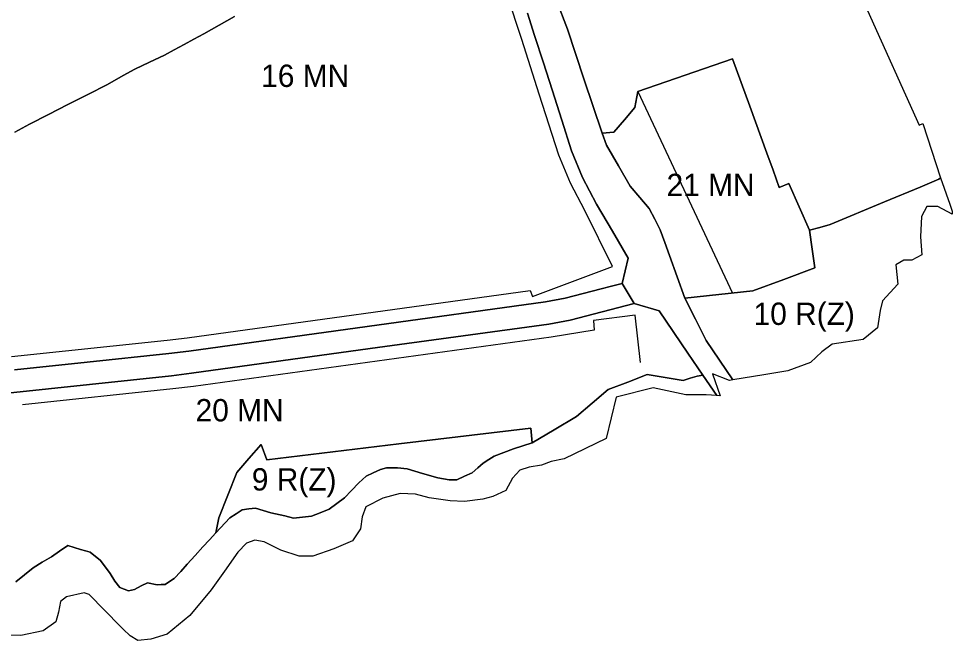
# Model space of a CAD drawing. Extents: x 7423432 to 7425824, y 5537848 to 5539677.
# Drawn here: x 7425406.3 to 7425824.2, y 5538340.3 to 5538618.6 of the extents above; entities that cross this region are included whole.
import ezdxf

# ---------------------------------------------------------------- set-up
doc = ezdxf.new("R2010")
doc.units = 0
for name, color, linetype in [('linie_rozgraniczajace', 7, 'Continuous'), ('linie_zabudowy_nieprzekraczalne', 7, 'Continuous'), ('oznaczenia_przeznaczen', 7, 'Continuous')]:
    doc.layers.add(name, color=color, linetype=linetype)

msp = doc.modelspace()

# ---------------------------------------------------------------- linework, layer by layer
at = {"layer": 'linie_rozgraniczajace'}
for points in [[(7425647.02, 5538626.8), (7425651.9, 5538613.83), (7425659.28, 5538591.74), (7425667.45, 5538567.39), (7425669.38, 5538561.96), (7425674.73, 5538552.77), (7425680.09, 5538543.59), (7425684.33, 5538538.58), (7425688.57, 5538533.57), (7425691.01, 5538528.83), (7425693.45, 5538524.08), (7425695.53, 5538518.35), (7425697.6, 5538512.61), (7425701.06, 5538503.05), (7425704.51, 5538493.5), (7425709.27, 5538484.03), (7425714.02, 5538474.57), (7425720.02, 5538465.74), (7425726.02, 5538456.91), (7425724.4, 5538456.65), (7425716.82, 5538459.58), (7425720.35, 5538449.71), (7425718.74, 5538449.83), (7425712.56, 5538458.93), (7425712.56, 5538458.93), (7425705.86, 5538468.79), (7425692.97, 5538487.75), (7425681.75, 5538491.09), (7425676.5, 5538500.06), (7425679.14, 5538511.37), (7425672.07, 5538523.46), (7425664.99, 5538535.55), (7425658.72, 5538547.53), (7425653.76, 5538559.49), (7425649.41, 5538573.09), (7425645.06, 5538586.69), (7425641.16, 5538598.87), (7425637.26, 5538611.05), (7425634, 5538621.14)], [(7425786.3, 5538622.32), (7425809.43, 5538570.89), (7425811.03, 5538571.65), (7425818.96, 5538547.35), (7425818.22, 5538546.7), (7425809.86, 5538543.23), (7425793.85, 5538536.59), (7425769.47, 5538526.47), (7425764.84, 5538525.17), (7425760.21, 5538523.87), (7425755.6, 5538534.37), (7425751, 5538544.87), (7425746.71, 5538543.08), (7425743.98, 5538550.73), (7425741.25, 5538558.37), (7425733.56, 5538579.47), (7425725.87, 5538600.56), (7425704.66, 5538593.28), (7425683.46, 5538585.99), (7425682.18, 5538578.88), (7425677.43, 5538573.32), (7425672.68, 5538567.76), (7425667.45, 5538567.39), (7425659.28, 5538591.74), (7425651.9, 5538613.83), (7425647.02, 5538626.8)], [(7425634, 5538621.14), (7425637.26, 5538611.05), (7425641.16, 5538598.87), (7425645.06, 5538586.69), (7425649.41, 5538573.09), (7425653.76, 5538559.49), (7425658.72, 5538547.53), (7425664.99, 5538535.55), (7425672.07, 5538523.46), (7425679.14, 5538511.37), (7425676.5, 5538500.06), (7425671.7, 5538498.81), (7425667.09, 5538497.61), (7425650.96, 5538493.45), (7425642.07, 5538491.75), (7425562.27, 5538480.77), (7425482.47, 5538469.79), (7425473.54, 5538468.7), (7425437.03, 5538464.83), (7425404.51, 5538461.39)], [(7425404.56, 5538567.83), (7425411.17, 5538571.43), (7425419.76, 5538575.77), (7425428.35, 5538580.1), (7425437.25, 5538584.6), (7425446.05, 5538589.06), (7425453.11, 5538593.1), (7425458.27, 5538596.06), (7425464.93, 5538599.13), (7425471.58, 5538602.19), (7425475.97, 5538604.58), (7425480.36, 5538606.97), (7425484.78, 5538609.38), (7425489.2, 5538611.78), (7425496.08, 5538615.71), (7425502.97, 5538619.64)], [(7425502.97, 5538619.64), (7425496.08, 5538615.71), (7425489.2, 5538611.78), (7425484.78, 5538609.38), (7425480.36, 5538606.97), (7425475.97, 5538604.58), (7425471.58, 5538602.19), (7425464.93, 5538599.13), (7425458.27, 5538596.06), (7425453.11, 5538593.1), (7425446.05, 5538589.06), (7425437.25, 5538584.6), (7425428.35, 5538580.1), (7425419.76, 5538575.77), (7425411.17, 5538571.43), (7425404.56, 5538567.83)], [(7425404.51, 5538461.39), (7425437.03, 5538464.83), (7425473.54, 5538468.7), (7425482.47, 5538469.79), (7425562.27, 5538480.77), (7425642.07, 5538491.75), (7425650.96, 5538493.45), (7425667.09, 5538497.61), (7425671.7, 5538498.81), (7425676.5, 5538500.06), (7425681.75, 5538491.09), (7425653.13, 5538483.68), (7425643.68, 5538481.88), (7425563.72, 5538470.88), (7425483.76, 5538459.87), (7425474.67, 5538458.76), (7425438.03, 5538454.88), (7425401.39, 5538451)], [(7425401.39, 5538451), (7425438.03, 5538454.88), (7425474.67, 5538458.76), (7425483.76, 5538459.87), (7425563.72, 5538470.88), (7425643.68, 5538481.88), (7425653.13, 5538483.68), (7425681.75, 5538491.09), (7425692.97, 5538487.75), (7425705.86, 5538468.79), (7425712.56, 5538458.93), (7425712.56, 5538458.93), (7425710.07, 5538458.55), (7425706.92, 5538457.58), (7425703.77, 5538456.61), (7425695.72, 5538457.97), (7425687.68, 5538459.32), (7425678.91, 5538455.92), (7425670.15, 5538452.52), (7425663.05, 5538446.47), (7425655.95, 5538440.42), (7425646.04, 5538434.56), (7425636.14, 5538428.7), (7425635.51, 5538435.3), (7425576.49, 5538428.19), (7425517.47, 5538421.09), (7425514.85, 5538427.96), (7425509.42, 5538421.71), (7425503.99, 5538415.46), (7425499.93, 5538405.31), (7425495.86, 5538395.16), (7425494.6, 5538388.45), (7425491.71, 5538385.26), (7425488.81, 5538382.07), (7425485.28, 5538378.18), (7425481.75, 5538374.29), (7425478.85, 5538371.09), (7425475.96, 5538367.89), (7425473.92, 5538366.56), (7425471.88, 5538365.23), (7425470.14, 5538365.19), (7425468.39, 5538365.15), (7425463.98, 5538366.08), (7425461.1, 5538364.59), (7425458.22, 5538363.09), (7425455.47, 5538362.43), (7425451.69, 5538363.92), (7425449.31, 5538366.82), (7425447.24, 5538370.17), (7425442.93, 5538376.04), (7425438.41, 5538379.73), (7425436.25, 5538380.36), (7425434.09, 5538380.99), (7425428.37, 5538382.68), (7425424.69, 5538380.2), (7425421, 5538377.72), (7425416.89, 5538375.23), (7425412.78, 5538372.73), (7425408.89, 5538369.61), (7425405.01, 5538366.49)], [(7425428.37, 5538382.68), (7425434.09, 5538380.99), (7425436.25, 5538380.36), (7425438.41, 5538379.73), (7425442.93, 5538376.04), (7425447.24, 5538370.17), (7425449.31, 5538366.82), (7425451.69, 5538363.92), (7425455.47, 5538362.43), (7425458.22, 5538363.09), (7425461.1, 5538364.59), (7425463.98, 5538366.08), (7425468.39, 5538365.15), (7425470.14, 5538365.19), (7425471.88, 5538365.23), (7425473.92, 5538366.56), (7425475.96, 5538367.89), (7425478.85, 5538371.09), (7425481.75, 5538374.29), (7425485.28, 5538378.18), (7425488.81, 5538382.07), (7425491.71, 5538385.26), (7425494.6, 5538388.45), (7425500.88, 5538395.17), (7425503.63, 5538396.96), (7425506.37, 5538398.75), (7425509.32, 5538399.13), (7425512.27, 5538399.51), (7425519.15, 5538397.42), (7425525.44, 5538395.93), (7425529.29, 5538394.98), (7425533.33, 5538395.43), (7425537.37, 5538395.88), (7425541.35, 5538397.41), (7425545.33, 5538398.94), (7425548.73, 5538401.47), (7425552.12, 5538404), (7425555.36, 5538407.42), (7425558.59, 5538410.85), (7425560.2, 5538412.32), (7425561.8, 5538413.8), (7425565.06, 5538415.3), (7425568.32, 5538416.8), (7425570.92, 5538417.43), (7425573.41, 5538417.49), (7425575.9, 5538417.54), (7425580.25, 5538417.04), (7425587.12, 5538415.03), (7425594, 5538413.03), (7425596.54, 5538412.58), (7425599.08, 5538412.14), (7425602.51, 5538412.17), (7425605.93, 5538413.73), (7425609.35, 5538415.29), (7425611.82, 5538417.45), (7425614.29, 5538419.6), (7425616.74, 5538421.18), (7425619.18, 5538422.76), (7425623.49, 5538424.36), (7425627.79, 5538425.95), (7425631.96, 5538427.32), (7425636.14, 5538428.7), (7425646.04, 5538434.56), (7425655.95, 5538440.42), (7425663.05, 5538446.47), (7425670.15, 5538452.52), (7425678.91, 5538455.92), (7425687.68, 5538459.32), (7425695.72, 5538457.97), (7425703.77, 5538456.61), (7425706.92, 5538457.58), (7425710.07, 5538458.55), (7425712.56, 5538458.93), (7425718.74, 5538449.83), (7425714.05, 5538450.18), (7425704.94, 5538450.24), (7425690.27, 5538453.27), (7425673.76, 5538449.14), (7425669.23, 5538430.69), (7425650.51, 5538421.49), (7425644.71, 5538420.32), (7425640.33, 5538418.75), (7425634.87, 5538417.8), (7425630.65, 5538416.49), (7425627.29, 5538412.84), (7425624.3, 5538407.33), (7425618.62, 5538404.61), (7425614.08, 5538403.51), (7425605.93, 5538402.45), (7425599.42, 5538402.79), (7425590.07, 5538404.03), (7425583.94, 5538405.71), (7425577.15, 5538405.97), (7425569.37, 5538403.84), (7425561.78, 5538400.02), (7425560.05, 5538395.55), (7425559.28, 5538390.23), (7425555.8, 5538384.88), (7425547.36, 5538381.17), (7425538.01, 5538378.01)], [(7425538.01, 5538378.01), (7425531.89, 5538377.9), (7425523.6, 5538380.68), (7425516.28, 5538384.37), (7425512.01, 5538385.14), (7425508.24, 5538383.75), (7425504.4, 5538379.75), (7425498.43, 5538371.17), (7425492.46, 5538362.86), (7425482.97, 5538351.43), (7425472.81, 5538343.09), (7425465.53, 5538340.82), (7425459.61, 5538340.26), (7425456.27, 5538342.31), (7425453.14, 5538345.19), (7425451.74, 5538346.61), (7425437.87, 5538360.78), (7425435.7, 5538361.55), (7425427.78, 5538359.76), (7425425.04, 5538357.65), (7425424.2, 5538352.81), (7425422.94, 5538348.57), (7425417.31, 5538344.55), (7425407.26, 5538342.36), (7425399.61, 5538342.57)], [(7425405.01, 5538366.49), (7425408.89, 5538369.61), (7425412.78, 5538372.73), (7425416.89, 5538375.23), (7425421, 5538377.72), (7425424.69, 5538380.2), (7425428.37, 5538382.68)]]:
    msp.add_lwpolyline(points, dxfattribs=at)
for points in [[(7425667.45, 5538567.39), (7425672.68, 5538567.76), (7425677.43, 5538573.32), (7425682.18, 5538578.88), (7425683.46, 5538585.99), (7425704.66, 5538593.28), (7425725.87, 5538600.56), (7425733.56, 5538579.47), (7425741.25, 5538558.37), (7425743.98, 5538550.73), (7425746.71, 5538543.08), (7425751, 5538544.87), (7425755.6, 5538534.37), (7425760.21, 5538523.87), (7425761.41, 5538515.45), (7425762.62, 5538507.02), (7425748.76, 5538501.86), (7425734.9, 5538496.7), (7425719.71, 5538495.09), (7425704.51, 5538493.5), (7425701.06, 5538503.05), (7425697.6, 5538512.61), (7425695.53, 5538518.35), (7425693.45, 5538524.08), (7425691.01, 5538528.83), (7425688.57, 5538533.57), (7425684.33, 5538538.58), (7425680.09, 5538543.59), (7425674.73, 5538552.77), (7425669.38, 5538561.96)], [(7425704.51, 5538493.5), (7425719.71, 5538495.09), (7425734.9, 5538496.7), (7425748.76, 5538501.86), (7425762.62, 5538507.02), (7425761.41, 5538515.45), (7425760.21, 5538523.87), (7425764.84, 5538525.17), (7425769.47, 5538526.47), (7425793.85, 5538536.59), (7425809.86, 5538543.23), (7425818.22, 5538546.7), (7425818.96, 5538547.35), (7425823.12, 5538535.53), (7425824.2, 5538532.44), (7425824.19, 5538531.06), (7425817.66, 5538534.52), (7425812.83, 5538534.53), (7425810.46, 5538530.03), (7425810.02, 5538520.85), (7425810.54, 5538512.93), (7425806.15, 5538510.5), (7425802.45, 5538510.51), (7425798.9, 5538508.33), (7425799.74, 5538499.69), (7425793.01, 5538492.2), (7425791.95, 5538487.96), (7425790.75, 5538480.13), (7425784.23, 5538474.97), (7425770.36, 5538472.83), (7425765.77, 5538469.45), (7425760.75, 5538464.65), (7425750.53, 5538461), (7425739.91, 5538459.15), (7425726.02, 5538456.91), (7425720.02, 5538465.74), (7425714.02, 5538474.57), (7425709.27, 5538484.03)], [(7425494.6, 5538388.45), (7425495.86, 5538395.16), (7425499.93, 5538405.31), (7425503.99, 5538415.46), (7425509.42, 5538421.71), (7425514.85, 5538427.96), (7425517.47, 5538421.09), (7425576.49, 5538428.19), (7425635.51, 5538435.3), (7425636.14, 5538428.7), (7425631.96, 5538427.32), (7425627.79, 5538425.95), (7425623.49, 5538424.36), (7425619.18, 5538422.76), (7425616.74, 5538421.18), (7425614.29, 5538419.6), (7425611.82, 5538417.45), (7425609.35, 5538415.29), (7425605.93, 5538413.73), (7425602.51, 5538412.17), (7425599.08, 5538412.14), (7425596.54, 5538412.58), (7425594, 5538413.03), (7425587.12, 5538415.03), (7425580.25, 5538417.04), (7425575.9, 5538417.54), (7425573.41, 5538417.49), (7425570.92, 5538417.43), (7425568.32, 5538416.8), (7425565.06, 5538415.3), (7425561.8, 5538413.8), (7425560.2, 5538412.32), (7425558.59, 5538410.85), (7425555.36, 5538407.42), (7425552.12, 5538404), (7425548.73, 5538401.47), (7425545.33, 5538398.94), (7425541.35, 5538397.41), (7425537.37, 5538395.88), (7425533.33, 5538395.43), (7425529.29, 5538394.98), (7425525.44, 5538395.93), (7425519.15, 5538397.42), (7425512.27, 5538399.51), (7425509.32, 5538399.13), (7425506.37, 5538398.75), (7425503.63, 5538396.96), (7425500.88, 5538395.17)]]:
    msp.add_lwpolyline(points, close=True, dxfattribs=at)
at = {"layer": 'linie_zabudowy_nieprzekraczalne'}
for points in [[(7425403.1, 5538467.28), (7425472.86, 5538474.66), (7425481.7, 5538475.74), (7425635.24, 5538496.85), (7425636.24, 5538494.22), (7425636.24, 5538494.22), (7425672.06, 5538507.66), (7425659.74, 5538532.64), (7425653.28, 5538544.99), (7425648.13, 5538557.43), (7425639.35, 5538584.86), (7425631.55, 5538609.21), (7425625.04, 5538629.34), (7425617.08, 5538652.83), (7425612.13, 5538667.84), (7425599.82, 5538705.08), (7425596.78, 5538715.41), (7425584.84, 5538771.82), (7425577.47, 5538810.31), (7425570.88, 5538837.86)], [(7425683.46, 5538585.99), (7425725.77, 5538495.73)], [(7425684.69, 5538464.59), (7425682.28, 5538485.88), (7425663.56, 5538483.4), (7425663.93, 5538479.17), (7425644.65, 5538475.96), (7425484.53, 5538453.92), (7425475.35, 5538452.8), (7425408.13, 5538445.68)]]:
    msp.add_lwpolyline(points, dxfattribs=at)

# ---------------------------------------------------------------- texts
at = {"layer": 'oznaczenia_przeznaczen'}
for s, p in [('16 MN', (7425514.88, 5538588.03)), ('21 MN', (7425696.3, 5538539.15)), ('10 R(Z)', (7425735.25, 5538481.47)), ('20 MN', (7425485.53, 5538438.29)), ('9 R(Z)', (7425510.7, 5538407.33))]:
    msp.add_text(s, height=10, dxfattribs=at).set_placement(p)

doc.saveas('drawing.dxf')
